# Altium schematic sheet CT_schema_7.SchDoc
size 218 x 258 mm
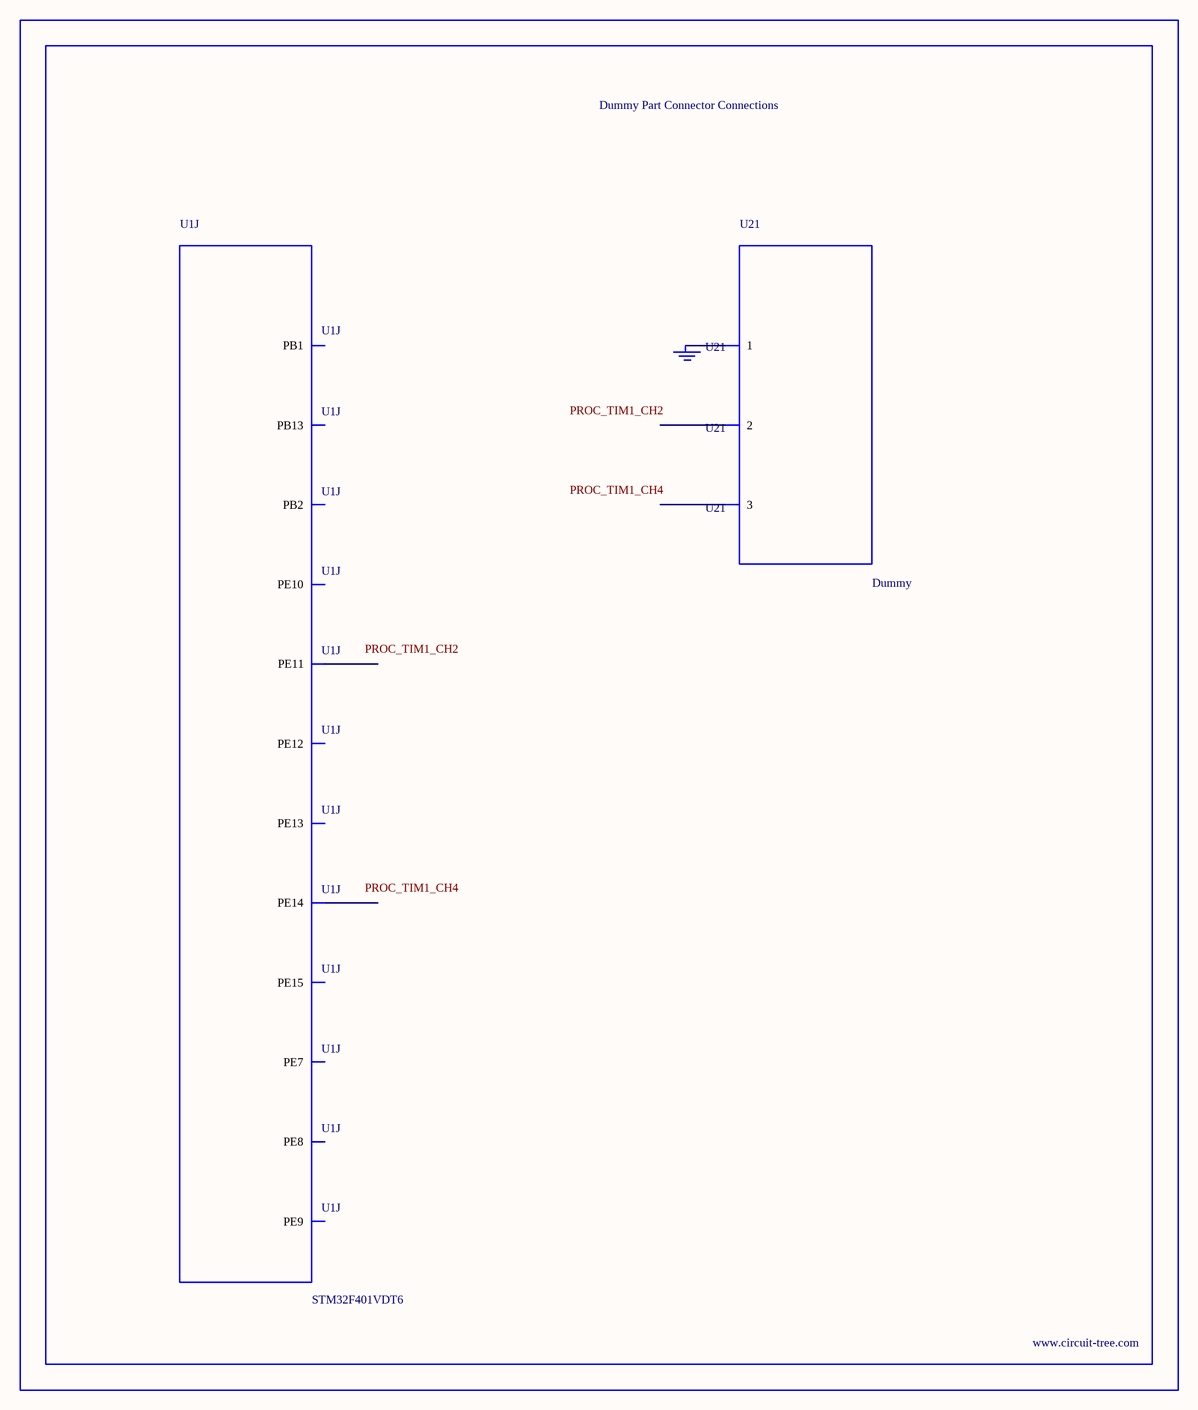
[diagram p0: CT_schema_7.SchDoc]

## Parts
BORDER6  (no value)
GND_INSTANCE_6_0  (no value)
U1  STM32F401VDT6  [LQFP100]  (part J of 10)
U21  Dummy  [DUMMY_PACKAGE_211]

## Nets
NetGND_INSTANCE_6_0_0: GND_INSTANCE_6_0.0(GND) U21.1

Not connected (* = marked no-connect by the designer): U1 36(PB1) 37(PB2) 38(PE7) 39(PE8) 40(PE9) 41(PE10) 42(PE11) 43(PE12) 44(PE13) 45(PE14) 46(PE15) 52(PB13); U21 2 3

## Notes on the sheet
- Labels drawn without touching a wire or pin: PROC_TIM1_CH2, PROC_TIM1_CH4

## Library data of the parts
BORDER6 = BORDER_PAGE6
GND_INSTANCE_6_0 = GND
